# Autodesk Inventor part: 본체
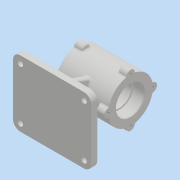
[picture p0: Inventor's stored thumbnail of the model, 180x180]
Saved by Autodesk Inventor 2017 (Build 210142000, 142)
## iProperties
Part Number: 본체
Material: 일반
Document SubType Name: Modeling
Designer: MRC
Density: 1 g/cm^3
Appearance: 기본값
Author: MRC
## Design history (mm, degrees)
sketch "스케치1"
  geometry: L1 (-70.407, 0)-(70.407, 0); L2 (-43.5, 23.5)-(-43.5, 37); L3 (-43.5, 37)-(43.5, 37); L4 (43.5, 37)-(43.5, 23.5); L5 (-43.5, 23.5)-(-24.5, 23.5); L6 (-24.5, 23.5)-(-24.5, 21); L7 (-24.5, 21)-(24.5, 21); L8 (24.5, 21)-(24.5, 23.5); L9 (24.5, 23.5)-(43.5, 23.5); 3 further points
  constraints: 18 end point, 6 perpendicular, 2 midpoint, 2 point on line, 1 coincident, 1 collinear, 1 horizontal, 1 vertical, 1 vertical alignment
  dimensions: "d0" = 74 diameter of L3 L1; "d1" = 87 distance of L2.end L3.end; "d2" = 47 diameter of L5 L1; "d3" = 42 diameter of L7 L1; "d4" = 19 distance of L2.start L5.end
revolve "회전1" sketch "스케치1" stored, may be unused: angle "d5" = 90 deg
sketch "스케치2"
  geometry: C1 r 7 at (0, 37); 2 further points
  constraints: 2 vertical alignment, 1 centre point, 1 other
  dimensions: "d6" = 14 diameter of C1
extrude "돌출1" join sketch "스케치2" distance "d7" = 14; taper "d8" = 0 deg
fillet "모깎기1" dims "d9" = 3
sketch "스케치3"
  geometry: 3 further points
  constraints: 1 vertical alignment, 1 other
hole "구멍1" sketch "스케치3" at (0, 0) diameter "d10" = 3.242; stored, may be unused: countersink angle "d14" = 90 deg, drill point angle "d16" = 118 deg; dims "d11" = 8, "d12" = 4, "d13" = 2, "d15" = 10
chamfer "모따기1" distance "d20" = 1; stored, may be unused: second distance "d21" = 2, angle "d22" = 45 deg
node "작업 평면1"
sketch "스케치4"
  geometry: L1 (-48, -55)-(58, -55); L2 (70, -43)-(70, 43); L3 (58, 55)-(-48, 55); L4 (-60, 43)-(-60, -43); C1 r 4.5 at (58, -43); C2 r 4.5 at (58, 43); C3 r 4.5 at (-48, 43); C4 r 4.5 at (-48, -43); A1 r 12 centre (58, -43) between (58, -55) and (70, -43); A2 r 12 centre (58, 43) between (70, 43) and (58, 55); A3 r 12 centre (-48, 43) between (-48, 55) and (-60, 43); A4 r 12 centre (-48, -43) between (-60, -43) and (-48, -55); 5 further points
  constraints: 8 centre point, 8 end point, 8 point on circle, 8 tangent, 6 point on line, 4 coincident, 3 equal radius, 2 parallel, 1 horizontal, 1 horizontal alignment, 1 midpoint, 1 perpendicular
  dimensions: "d24" = 130 distance of point (-60, -55) point (70, -55); "d25" = 110 distance of point (-60, 55) point (-60, -55); "d26" = 70 distance from line of L2 point (0, 0); "d27" = 12 radius of A1; "d28" = 9 diameter of C1; "d29" = 9 diameter of C2; "d30" = 9 diameter of C3; "d31" = 9 diameter of C4
extrude "돌출2" join sketch "스케치4" distance "d32" = 12; taper "d33" = 0 deg
sketch "스케치5"
  geometry: L1 (5, -5)-(-5, -5); L2 (-5, -5)-(-5, 5); L3 (-5, 5)-(5, 5); L4 (5, 5)-(5, -5); 3 further points
  constraints: 8 end point, 2 midpoint, 2 parallel, 1 horizontal, 1 horizontal alignment, 1 perpendicular, 1 vertical alignment
  dimensions: "d34" = 10 distance of L3.end L1.start; "d35" = 10 distance of L1.start L1.end
extrude "돌출3" join sketch "스케치5" stored distance "d36" = 10; taper "d37" = 0 deg
sketch "스케치6"
  geometry: L1 (16.172, -32.008)-(30, -70); L2 (-58, -70)-(48, -70) reference; 1 further point
  constraints: 2 end point, 1 point on line
  dimensions: "d38" = 110 deg angle of L2 L1; "d39" = 30 horizontal distance of point (0, 0) L1.end
feature "리브1" sketch "스케치6" dims "d40" = 1, "d41" = 10, "d42" = 0, "d43" = 0, "d44" = 1, "d45" = 1
sketch "스케치7"
  geometry: L1 (-70, -43)-(-70, 43) reference; L2 (-70, 41)-(-23.638, 24.126); L3 (-82, 55)-(-70, 55) reference; 1 further point
  constraints: 2 end point, 1 point on line
  dimensions: "d46" = 110 deg angle of L1 L2; "d47" = 14 distance from line of L3 L2.start
feature "리브2" sketch "스케치7" dims "d48" = 1, "d49" = 10, "d50" = 0, "d51" = 0, "d52" = 1, "d53" = 1
fillet "모깎기2" dims "d54" = 3
fillet "모깎기3" dims "d58" = 1
sketch "스케치10"
  geometry: L1 (-54.998, 20.739)-(-54.998, -20.739); L2 (-54.998, -20.739)-(-61.002, -20.739); L3 (-61.002, -20.739)-(-61.002, 20.739); L4 (-61.002, 20.739)-(-54.998, 20.739); 4 further points
  constraints: 2 horizontal alignment, 1 vertical alignment, 2 other
  dimensions: "d62" = 58 distance of point (-58, 0) point (0, 0)
feature "엠보싱3" sketch "스케치10" dims "d63" = 0.5, "d64" = 0
node "솔리드1"
pattern_circular "원형 패턴1" dims angle "d18" = 360 deg
mirror "미러1"
mirror "미러2"
mirror "미러3"
other parameters: "d23" = -82
